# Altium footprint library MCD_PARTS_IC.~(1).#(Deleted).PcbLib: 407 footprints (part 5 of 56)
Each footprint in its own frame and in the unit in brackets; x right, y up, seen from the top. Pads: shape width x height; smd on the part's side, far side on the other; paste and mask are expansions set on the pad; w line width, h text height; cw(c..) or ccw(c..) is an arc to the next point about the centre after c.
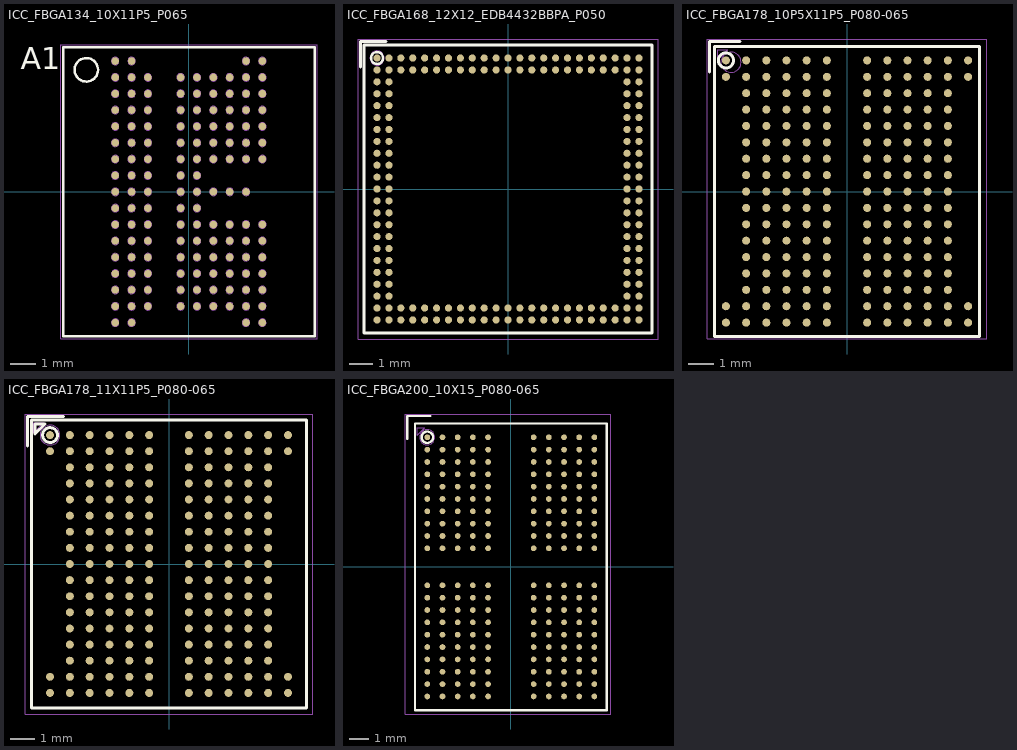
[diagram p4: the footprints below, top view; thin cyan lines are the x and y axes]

## ICC_FBGA134_10X11P5_P065 [mm] "MCD-02167"
height 0.8
pads (134):
  round 0.3 smd mask+0.05: A1(-2.925,5.2) A2(-2.275,5.2) A9(2.275,5.2) A10(2.925,5.2) B1(-2.925,4.55) B2(-2.275,4.55) B3(-1.625,4.55) B5(-0.325,4.55) B6(0.325,4.55) B7(0.975,4.55) B8(1.625,4.55) B9(2.275,4.55) B10(2.925,4.55) C1(-2.925,3.9) C2(-2.275,3.9) C3(-1.625,3.9) C5(-0.325,3.9) C6(0.325,3.9) C7(0.975,3.9) C8(1.625,3.9) C9(2.275,3.9) C10(2.925,3.9) D1(-2.925,3.25) D2(-2.275,3.25) D3(-1.625,3.25) D5(-0.325,3.25) D6(0.325,3.25) D7(0.975,3.25) D8(1.625,3.25) D9(2.275,3.25) D10(2.925,3.25) E1(-2.925,2.6) E2(-2.275,2.6) E3(-1.625,2.6) E5(-0.325,2.6) E6(0.325,2.6) E7(0.975,2.6) E8(1.625,2.6) E9(2.275,2.6) E10(2.925,2.6) F1(-2.925,1.95) F2(-2.275,1.95) F3(-1.625,1.95) F5(-0.325,1.95) F6(0.325,1.95) F7(0.975,1.95) F8(1.625,1.95) F9(2.275,1.95) F10(2.925,1.95) G1(-2.925,1.3) G2(-2.275,1.3) G3(-1.625,1.3) G5(-0.325,1.3) G6(0.325,1.3) G7(0.975,1.3) G8(1.625,1.3) G9(2.275,1.3) G10(2.925,1.3) H1(-2.925,0.65) H2(-2.275,0.65) H3(-1.625,0.65) H5(-0.325,0.65) H6(0.325,0.65) J1(-2.925,0) J2(-2.275,0) J3(-1.625,0) J5(-0.325,0) J6(0.325,0) J7(0.975,0) J8(1.625,0) J9(2.275,0) K1(-2.925,-0.65) K2(-2.275,-0.65) K3(-1.625,-0.65) K5(-0.325,-0.65) K6(0.325,-0.65) L1(-2.925,-1.3) L2(-2.275,-1.3) L3(-1.625,-1.3) L5(-0.325,-1.3) L6(0.325,-1.3) L7(0.975,-1.3) L8(1.625,-1.3) L9(2.275,-1.3) L10(2.925,-1.3) M1(-2.925,-1.95) M2(-2.275,-1.95) M3(-1.625,-1.95) M5(-0.325,-1.95) M6(0.325,-1.95) M7(0.975,-1.95) M8(1.625,-1.95) M9(2.275,-1.95) M10(2.925,-1.95) N1(-2.925,-2.6) N2(-2.275,-2.6) N3(-1.625,-2.6) N5(-0.325,-2.6) N6(0.325,-2.6) N7(0.975,-2.6) N8(1.625,-2.6) N9(2.275,-2.6) N10(2.925,-2.6) P1(-2.925,-3.25) P2(-2.275,-3.25) P3(-1.625,-3.25) P5(-0.325,-3.25) P6(0.325,-3.25) P7(0.975,-3.25) P8(1.625,-3.25) P9(2.275,-3.25) P10(2.925,-3.25) R1(-2.925,-3.9) R2(-2.275,-3.9) R3(-1.625,-3.9) R5(-0.325,-3.9) R6(0.325,-3.9) R7(0.975,-3.9) R8(1.625,-3.9) R9(2.275,-3.9) R10(2.925,-3.9) T1(-2.925,-4.55) T2(-2.275,-4.55) T3(-1.625,-4.55) T5(-0.325,-4.55) T6(0.325,-4.55) T7(0.975,-4.55) T8(1.625,-4.55) T9(2.275,-4.55) T10(2.925,-4.55) U1(-2.925,-5.2) U2(-2.275,-5.2) U9(2.275,-5.2) U10(2.925,-5.2)
Top Overlay:
  circle w0.1: c-4.075,4.85 r0.467
  lines w0.1: -5,-5.75 5,-5.75 5,5.75 -5,5.75 -5,-5.75
  text "A1" at -6.675,4.575 h1.5
M14-Top Assembly:
  circle w0.01: c-2.925,-5.2 r0.15
  circle w0.01: c-2.275,-5.2 r0.15
  circle w0.01: c2.275,-5.2 r0.15
  circle w0.01: c2.925,-5.2 r0.15
  circle w0.01: c-2.925,-4.55 r0.15
  circle w0.01: c-2.275,-4.55 r0.15
  circle w0.01: c-1.625,-4.55 r0.15
  circle w0.01: c-0.325,-4.55 r0.15
  circle w0.01: c0.325,-4.55 r0.15
  circle w0.01: c0.975,-4.55 r0.15
  circle w0.01: c1.625,-4.55 r0.15
  circle w0.01: c2.275,-4.55 r0.15
  circle w0.01: c2.925,-4.55 r0.15
  circle w0.01: c-2.925,-3.9 r0.15
  circle w0.01: c-2.275,-3.9 r0.15
  circle w0.01: c-1.625,-3.9 r0.15
  circle w0.01: c-0.325,-3.9 r0.15
  circle w0.01: c0.325,-3.9 r0.15
  circle w0.01: c0.975,-3.9 r0.15
  circle w0.01: c1.625,-3.9 r0.15
  circle w0.01: c2.275,-3.9 r0.15
  circle w0.01: c2.925,-3.9 r0.15
  circle w0.01: c-2.925,-3.25 r0.15
  circle w0.01: c-2.275,-3.25 r0.15
  circle w0.01: c-1.625,-3.25 r0.15
  circle w0.01: c-0.325,-3.25 r0.15
  circle w0.01: c0.325,-3.25 r0.15
  circle w0.01: c0.975,-3.25 r0.15
  circle w0.01: c1.625,-3.25 r0.15
  circle w0.01: c2.275,-3.25 r0.15
  circle w0.01: c2.925,-3.25 r0.15
  circle w0.01: c-2.925,-2.6 r0.15
  circle w0.01: c-2.275,-2.6 r0.15
  circle w0.01: c-1.625,-2.6 r0.15
  circle w0.01: c-0.325,-2.6 r0.15
  circle w0.01: c0.325,-2.6 r0.15
  circle w0.01: c0.975,-2.6 r0.15
  circle w0.01: c1.625,-2.6 r0.15
  circle w0.01: c2.275,-2.6 r0.15
  circle w0.01: c2.925,-2.6 r0.15
  circle w0.01: c-2.925,-1.95 r0.15
  circle w0.01: c-2.275,-1.95 r0.15
  circle w0.01: c-1.625,-1.95 r0.15
  circle w0.01: c-0.325,-1.95 r0.15
  circle w0.01: c0.325,-1.95 r0.15
  circle w0.01: c0.975,-1.95 r0.15
  circle w0.01: c1.625,-1.95 r0.15
  circle w0.01: c2.275,-1.95 r0.15
  circle w0.01: c2.925,-1.95 r0.15
  circle w0.01: c-2.925,-1.3 r0.15
  circle w0.01: c-2.275,-1.3 r0.15
  circle w0.01: c-1.625,-1.3 r0.15
  circle w0.01: c-0.325,-1.3 r0.15
  circle w0.01: c0.325,-1.3 r0.15
  circle w0.01: c0.975,-1.3 r0.15
  circle w0.01: c1.625,-1.3 r0.15
  circle w0.01: c2.275,-1.3 r0.15
  circle w0.01: c2.925,-1.3 r0.15
  circle w0.01: c-2.925,-0.65 r0.15
  circle w0.01: c-2.275,-0.65 r0.15
  circle w0.01: c-1.625,-0.65 r0.15
  circle w0.01: c-0.325,-0.65 r0.15
  circle w0.01: c0.325,-0.65 r0.15
  circle w0.01: c-2.925,0 r0.15
  circle w0.01: c-2.275,0 r0.15
  circle w0.01: c-1.625,0 r0.15
  circle w0.01: c-0.325,0 r0.15
  circle w0.01: c0.325,0 r0.15
  circle w0.01: c0.975,0 r0.15
  circle w0.01: c1.625,0 r0.15
  circle w0.01: c2.275,0 r0.15
  circle w0.01: c-2.925,0.65 r0.15
  circle w0.01: c-2.275,0.65 r0.15
  circle w0.01: c-1.625,0.65 r0.15
  circle w0.01: c-0.325,0.65 r0.15
  circle w0.01: c0.325,0.65 r0.15
  circle w0.01: c-2.925,1.3 r0.15
  circle w0.01: c-2.275,1.3 r0.15
  circle w0.01: c-1.625,1.3 r0.15
  circle w0.01: c-0.325,1.3 r0.15
  circle w0.01: c0.325,1.3 r0.15
  circle w0.01: c0.975,1.3 r0.15
  circle w0.01: c1.625,1.3 r0.15
  circle w0.01: c2.275,1.3 r0.15
  circle w0.01: c2.925,1.3 r0.15
  circle w0.01: c-2.925,1.95 r0.15
  circle w0.01: c-2.275,1.95 r0.15
  circle w0.01: c-1.625,1.95 r0.15
  circle w0.01: c-0.325,1.95 r0.15
  circle w0.01: c0.325,1.95 r0.15
  circle w0.01: c0.975,1.95 r0.15
  circle w0.01: c1.625,1.95 r0.15
  circle w0.01: c2.275,1.95 r0.15
  circle w0.01: c2.925,1.95 r0.15
  circle w0.01: c-2.925,2.6 r0.15
  circle w0.01: c-2.275,2.6 r0.15
  circle w0.01: c-1.625,2.6 r0.15
  circle w0.01: c-0.325,2.6 r0.15
  circle w0.01: c0.325,2.6 r0.15
  circle w0.01: c0.975,2.6 r0.15
  circle w0.01: c1.625,2.6 r0.15
  circle w0.01: c2.275,2.6 r0.15
  circle w0.01: c2.925,2.6 r0.15
  circle w0.01: c-2.925,3.25 r0.15
  circle w0.01: c-2.275,3.25 r0.15
  circle w0.01: c-1.625,3.25 r0.15
  circle w0.01: c-0.325,3.25 r0.15
  circle w0.01: c0.325,3.25 r0.15
  circle w0.01: c0.975,3.25 r0.15
  circle w0.01: c1.625,3.25 r0.15
  circle w0.01: c2.275,3.25 r0.15
  circle w0.01: c2.925,3.25 r0.15
  circle w0.01: c-2.925,3.9 r0.15
  circle w0.01: c-2.275,3.9 r0.15
  circle w0.01: c-1.625,3.9 r0.15
  circle w0.01: c-0.325,3.9 r0.15
  circle w0.01: c0.325,3.9 r0.15
  circle w0.01: c0.975,3.9 r0.15
  circle w0.01: c1.625,3.9 r0.15
  circle w0.01: c2.275,3.9 r0.15
  circle w0.01: c2.925,3.9 r0.15
  circle w0.01: c2.925,4.55 r0.15
  circle w0.01: c2.275,4.55 r0.15
  circle w0.01: c1.625,4.55 r0.15
  circle w0.01: c0.975,4.55 r0.15
  circle w0.01: c0.325,4.55 r0.15
  circle w0.01: c-0.325,4.55 r0.15
  circle w0.01: c-1.625,4.55 r0.15
  circle w0.01: c-2.275,4.55 r0.15
  circle w0.01: c-2.925,4.55 r0.15
  circle w0.01: c2.925,5.2 r0.15
  circle w0.01: c2.275,5.2 r0.15
  circle w0.01: c-2.275,5.2 r0.15
  circle w0.01: c-2.925,5.2 r0.15
  circle w0.01: c-4.075,4.85 r0.467
  lines w0.01: -5,-5.75 5,-5.75 5,5.75 -5,5.75 -5,-5.75
  text "A1" at -3.325,4.975 h0.7
  text "'.Designator'" at -2,-0.5 h0.75
M16-Top Courtyard:
  lines w0.01: -5.1,-5.85 5.1,-5.85 5.1,5.85 -5.1,5.85 -5.1,-5.85
3D body "User Library-FBGA 134 pin.STEP": height 0.88, standoff -0.02, extent -5,-5.75 5,5.75
3D body: height 0.81, standoff 0.8, extent -4.538,4.384 -3.608,5.316
3D body: height 0.8, standoff 0, extent -5,-5.75 5,5.75

## ICC_FBGA168_12X12_EDB4432BBPA_P050 [mm]
height 0.8
pads (168):
  round 0.3 smd mask+0.05: A1(-5.5,5.5) A2(-5,5.5) A3(-4.5,5.5) A4(-4,5.5) A5(-3.5,5.5) A6(-3,5.5) A7(-2.5,5.5) A8(-2,5.5) A9(-1.5,5.5) A10(-1,5.5) A11(-0.5,5.5) A12(0,5.5) A13(0.5,5.5) A14(1,5.5) A15(1.5,5.5) A16(2,5.5) A17(2.5,5.5) A18(3,5.5) A19(3.5,5.5) A20(4,5.5) A21(4.5,5.5) A22(5,5.5) A23(5.5,5.5) AA1(-5.5,-4.5) AA2(-5,-4.5) AA22(5,-4.5) AA23(5.5,-4.5) AB1(-5.5,-5) AB2(-5,-5) AB3(-4.5,-5) AB4(-4,-5) AB5(-3.5,-5) AB6(-3,-5) AB7(-2.5,-5) AB8(-2,-5) AB9(-1.5,-5) AB10(-1,-5) AB11(-0.5,-5) AB12(0,-5) AB13(0.5,-5) AB14(1,-5) AB15(1.5,-5) AB16(2,-5) AB17(2.5,-5) AB18(3,-5) AB19(3.5,-5) AB20(4,-5) AB21(4.5,-5) AB22(5,-5) AB23(5.5,-5) AC1(-5.5,-5.5) AC2(-5,-5.5) AC3(-4.5,-5.5) AC4(-4,-5.5) AC5(-3.5,-5.5) AC6(-3,-5.5) AC7(-2.5,-5.5) AC8(-2,-5.5) AC9(-1.5,-5.5) AC10(-1,-5.5) AC11(-0.5,-5.5) AC12(0,-5.5) AC13(0.5,-5.5) AC14(1,-5.5) AC15(1.5,-5.5) AC16(2,-5.5) AC17(2.5,-5.5) AC18(3,-5.5) AC19(3.5,-5.5) AC20(4,-5.5) AC21(4.5,-5.5) AC22(5,-5.5) AC23(5.5,-5.5) B1(-5.5,5) B2(-5,5) B3(-4.5,5) B4(-4,5) B5(-3.5,5) B6(-3,5) B7(-2.5,5) B8(-2,5) B9(-1.5,5) B10(-1,5) B11(-0.5,5) B12(0,5) B13(0.5,5) B14(1,5) B15(1.5,5) B16(2,5) B17(2.5,5) B18(3,5) B19(3.5,5) B20(4,5) B21(4.5,5) B22(5,5) B23(5.5,5) C1(-5.5,4.5) C2(-5,4.5) C22(5,4.5) C23(5.5,4.5) D1(-5.5,4) D2(-5,4) D22(5,4) D23(5.5,4) E1(-5.5,3.5) E2(-5,3.5) E22(5,3.5) E23(5.5,3.5) F1(-5.5,3) F2(-5,3) F22(5,3) F23(5.5,3) G1(-5.5,2.5) G2(-5,2.5) G22(5,2.5) G23(5.5,2.5) H1(-5.5,2) H2(-5,2) H22(5,2) H23(5.5,2) J1(-5.5,1.5) J2(-5,1.5) J22(5,1.5) J23(5.5,1.5) K1(-5.5,1) K2(-5,1) K22(5,1) K23(5.5,1) L1(-5.5,0.5) L2(-5,0.5) L22(5,0.5) L23(5.5,0.5) M1(-5.5,0) M2(-5,0) M22(5,0) M23(5.5,0) N1(-5.5,-0.5) N2(-5,-0.5) N22(5,-0.5) N23(5.5,-0.5) P1(-5.5,-1) P2(-5,-1) P22(5,-1) P23(5.5,-1) R1(-5.5,-1.5) R2(-5,-1.5) R22(5,-1.5) R23(5.5,-1.5) T1(-5.5,-2) T2(-5,-2) T22(5,-2) T23(5.5,-2) U1(-5.5,-2.5) U2(-5,-2.5) U22(5,-2.5) U23(5.5,-2.5) V1(-5.5,-3) V2(-5,-3) V22(5,-3) V23(5.5,-3) W1(-5.5,-3.5) W2(-5,-3.5) W22(5,-3.5) W23(5.5,-3.5) Y1(-5.5,-4) Y2(-5,-4) Y22(5,-4) Y23(5.5,-4)
Top Overlay:
  lines w0.1: -5.25,5.5 cw(c-5.5,5.5) -5.251,5.517
  lines w0.12: -6.2,5.125 -6.2,6.2 -5.125,6.2 ; -6.05,-6.05 -6.05,6.05 6.05,6.05 6.05,-6.05 -6.05,-6.05
M14-Top Assembly:
  circle w0.01: c-5.5,5.5 r0.3
  lines w0.01: -6.05,-6.05 -6.05,6.05 6.05,6.05 6.05,-6.05 -6.05,-6.05
  text "A1" at -5.85,5.275 h0.75
  text "'.Designator'" at -2,-0.5 h0.75
M16-Top Courtyard:
  lines w0.01: -6.3,-6.3 -6.3,6.3 6.3,6.3 6.3,-6.3 -6.3,-6.3
3D body: height 1.2, standoff 0, extent -6.355,-7.555 1.755,6.555
3D body: height 0.8, standoff 0, extent -6.05,-6.05 6.05,6.05
3D body: height 0.9, standoff 0.8, extent -5.548,4.951 -4.95,5.549

## ICC_FBGA178_10P5X11P5_P080-065 [mm] "MCD-02180"
height 0.83
pads (178):
  round 0.32 smd mask+0.05: A1(-4.8,5.2) A2(-4,5.2) A3(-3.2,5.2) A4(-2.4,5.2) A5(-1.6,5.2) A6(-0.8,5.2) A8(0.8,5.2) A9(1.6,5.2) A10(2.4,5.2) A11(3.2,5.2) A12(4,5.2) A13(4.8,5.2) B1(-4.8,4.55) B2(-4,4.55) B3(-3.2,4.55) B4(-2.4,4.55) B5(-1.6,4.55) B6(-0.8,4.55) B8(0.8,4.55) B9(1.6,4.55) B10(2.4,4.55) B11(3.2,4.55) B12(4,4.55) B13(4.8,4.55) C2(-4,3.9) C3(-3.2,3.9) C4(-2.4,3.9) C5(-1.6,3.9) C6(-0.8,3.9) C8(0.8,3.9) C9(1.6,3.9) C10(2.4,3.9) C11(3.2,3.9) C12(4,3.9) D2(-4,3.25) D3(-3.2,3.25) D4(-2.4,3.25) D5(-1.6,3.25) D6(-0.8,3.25) D8(0.8,3.25) D9(1.6,3.25) D10(2.4,3.25) D11(3.2,3.25) D12(4,3.25) E2(-4,2.6) E3(-3.2,2.6) E4(-2.4,2.6) E5(-1.6,2.6) E6(-0.8,2.6) E8(0.8,2.6) E9(1.6,2.6) E10(2.4,2.6) E11(3.2,2.6) E12(4,2.6) F2(-4,1.95) F3(-3.2,1.95) F4(-2.4,1.95) F5(-1.6,1.95) F6(-0.8,1.95) F8(0.8,1.95) F9(1.6,1.95) F10(2.4,1.95) F11(3.2,1.95) F12(4,1.95) G2(-4,1.3) G3(-3.2,1.3) G4(-2.4,1.3) G5(-1.6,1.3) G6(-0.8,1.3) G8(0.8,1.3) G9(1.6,1.3) G10(2.4,1.3) G11(3.2,1.3) G12(4,1.3) H2(-4,0.65) H3(-3.2,0.65) H4(-2.4,0.65) H5(-1.6,0.65) H6(-0.8,0.65) H8(0.8,0.65) H9(1.6,0.65) H10(2.4,0.65) H11(3.2,0.65) H12(4,0.65) J2(-4,0) J3(-3.2,0) J4(-2.4,0) J5(-1.6,0) J6(-0.8,0) J8(0.8,0) J9(1.6,0) J10(2.4,0) J11(3.2,0) J12(4,0) K2(-4,-0.65) K3(-3.2,-0.65) K4(-2.4,-0.65) K5(-1.6,-0.65) K6(-0.8,-0.65) K8(0.8,-0.65) K9(1.6,-0.65) K10(2.4,-0.65) K11(3.2,-0.65) K12(4,-0.65) L2(-4,-1.3) L3(-3.2,-1.3) L4(-2.4,-1.3) L5(-1.6,-1.3) L6(-0.8,-1.3) L8(0.8,-1.3) L9(1.6,-1.3) L10(2.4,-1.3) L11(3.2,-1.3) L12(4,-1.3) M2(-4,-1.95) M3(-3.2,-1.95) M4(-2.4,-1.95) M5(-1.6,-1.95) M6(-0.8,-1.95) M8(0.8,-1.95) M9(1.6,-1.95) M10(2.4,-1.95) M11(3.2,-1.95) M12(4,-1.95) N2(-4,-2.6) N3(-3.2,-2.6) N4(-2.4,-2.6) N5(-1.6,-2.6) N6(-0.8,-2.6) N8(0.8,-2.6) N9(1.6,-2.6) N10(2.4,-2.6) N11(3.2,-2.6) N12(4,-2.6) P2(-4,-3.25) P3(-3.2,-3.25) P4(-2.4,-3.25) P5(-1.6,-3.25) P6(-0.8,-3.25) P8(0.8,-3.25) P9(1.6,-3.25) P10(2.4,-3.25) P11(3.2,-3.25) P12(4,-3.25) R2(-4,-3.9) R3(-3.2,-3.9) R4(-2.4,-3.9) R5(-1.6,-3.9) R6(-0.8,-3.9) R8(0.8,-3.9) R9(1.6,-3.9) R10(2.4,-3.9) R11(3.2,-3.9) R12(4,-3.9) T1(-4.8,-4.55) T2(-4,-4.55) T3(-3.2,-4.55) T4(-2.4,-4.55) T5(-1.6,-4.55) T6(-0.8,-4.55) T8(0.8,-4.55) T9(1.6,-4.55) T10(2.4,-4.55) T11(3.2,-4.55) T12(4,-4.55) T13(4.8,-4.55) U1(-4.8,-5.2) U2(-4,-5.2) U3(-3.2,-5.2) U4(-2.4,-5.2) U5(-1.6,-5.2) U6(-0.8,-5.2) U8(0.8,-5.2) U9(1.6,-5.2) U10(2.4,-5.2) U11(3.2,-5.2) U12(4,-5.2) U13(4.8,-5.2)
Top Overlay:
  circle w0.12: c-4.8,5.2 r0.3
  lines w0.12: -5.45,4.75 -5.45,5.95 -4.25,5.95 ; -5.25,-5.75 5.25,-5.75 5.25,5.75 -5.25,5.75 -5.25,-5.75
M14-Top Assembly:
  circle w0.01: c-4.6,5.125 r0.4
  lines w0.01: -5.25,-5.75 -5.25,5.75 5.25,5.75 5.25,-5.75 -5.25,-5.75 ; -5.125,5.225 -5.125,5.625 -4.725,5.625 -5.125,5.225
  text "'.Designator'" at -2,-0.5 h0.75
  text "A1" at -4.95,4.9 h0.75
M16-Top Courtyard:
  lines w0.01: -5.55,-5.85 5.55,-5.85 5.55,6.05 -5.55,6.05 -5.55,-5.85
3D body: height 1, standoff 0, extent -5.25,-5.75 5.25,5.75
3D body: height 1.05, standoff 1, extent -5.098,4.901 -4.5,5.499

## ICC_FBGA178_11X11P5_P080-065 [mm]
height 1
pads (178):
  round 0.32 smd mask+0.05: A1(-4.8,5.2) A2(-4,5.2) A3(-3.2,5.2) A4(-2.4,5.2) A5(-1.6,5.2) A6(-0.8,5.2) A8(0.8,5.2) A9(1.6,5.2) A10(2.4,5.2) A11(3.2,5.2) A12(4,5.2) A13(4.8,5.2) B1(-4.8,4.55) B2(-4,4.55) B3(-3.2,4.55) B4(-2.4,4.55) B5(-1.6,4.55) B6(-0.8,4.55) B8(0.8,4.55) B9(1.6,4.55) B10(2.4,4.55) B11(3.2,4.55) B12(4,4.55) B13(4.8,4.55) C2(-4,3.9) C3(-3.2,3.9) C4(-2.4,3.9) C5(-1.6,3.9) C6(-0.8,3.9) C8(0.8,3.9) C9(1.6,3.9) C10(2.4,3.9) C11(3.2,3.9) C12(4,3.9) D2(-4,3.25) D3(-3.2,3.25) D4(-2.4,3.25) D5(-1.6,3.25) D6(-0.8,3.25) D8(0.8,3.25) D9(1.6,3.25) D10(2.4,3.25) D11(3.2,3.25) D12(4,3.25) E2(-4,2.6) E3(-3.2,2.6) E4(-2.4,2.6) E5(-1.6,2.6) E6(-0.8,2.6) E8(0.8,2.6) E9(1.6,2.6) E10(2.4,2.6) E11(3.2,2.6) E12(4,2.6) F2(-4,1.95) F3(-3.2,1.95) F4(-2.4,1.95) F5(-1.6,1.95) F6(-0.8,1.95) F8(0.8,1.95) F9(1.6,1.95) F10(2.4,1.95) F11(3.2,1.95) F12(4,1.95) G2(-4,1.3) G3(-3.2,1.3) G4(-2.4,1.3) G5(-1.6,1.3) G6(-0.8,1.3) G8(0.8,1.3) G9(1.6,1.3) G10(2.4,1.3) G11(3.2,1.3) G12(4,1.3) H2(-4,0.65) H3(-3.2,0.65) H4(-2.4,0.65) H5(-1.6,0.65) H6(-0.8,0.65) H8(0.8,0.65) H9(1.6,0.65) H10(2.4,0.65) H11(3.2,0.65) H12(4,0.65) J2(-4,0) J3(-3.2,0) J4(-2.4,0) J5(-1.6,0) J6(-0.8,0) J8(0.8,0) J9(1.6,0) J10(2.4,0) J11(3.2,0) J12(4,0) K2(-4,-0.65) K3(-3.2,-0.65) K4(-2.4,-0.65) K5(-1.6,-0.65) K6(-0.8,-0.65) K8(0.8,-0.65) K9(1.6,-0.65) K10(2.4,-0.65) K11(3.2,-0.65) K12(4,-0.65) L2(-4,-1.3) L3(-3.2,-1.3) L4(-2.4,-1.3) L5(-1.6,-1.3) L6(-0.8,-1.3) L8(0.8,-1.3) L9(1.6,-1.3) L10(2.4,-1.3) L11(3.2,-1.3) L12(4,-1.3) M2(-4,-1.95) M3(-3.2,-1.95) M4(-2.4,-1.95) M5(-1.6,-1.95) M6(-0.8,-1.95) M8(0.8,-1.95) M9(1.6,-1.95) M10(2.4,-1.95) M11(3.2,-1.95) M12(4,-1.95) N2(-4,-2.6) N3(-3.2,-2.6) N4(-2.4,-2.6) N5(-1.6,-2.6) N6(-0.8,-2.6) N8(0.8,-2.6) N9(1.6,-2.6) N10(2.4,-2.6) N11(3.2,-2.6) N12(4,-2.6) P2(-4,-3.25) P3(-3.2,-3.25) P4(-2.4,-3.25) P5(-1.6,-3.25) P6(-0.8,-3.25) P8(0.8,-3.25) P9(1.6,-3.25) P10(2.4,-3.25) P11(3.2,-3.25) P12(4,-3.25) R2(-4,-3.9) R3(-3.2,-3.9) R4(-2.4,-3.9) R5(-1.6,-3.9) R6(-0.8,-3.9) R8(0.8,-3.9) R9(1.6,-3.9) R10(2.4,-3.9) R11(3.2,-3.9) R12(4,-3.9) T1(-4.8,-4.55) T2(-4,-4.55) T3(-3.2,-4.55) T4(-2.4,-4.55) T5(-1.6,-4.55) T6(-0.8,-4.55) T8(0.8,-4.55) T9(1.6,-4.55) T10(2.4,-4.55) T11(3.2,-4.55) T12(4,-4.55) T13(4.8,-4.55) U1(-4.8,-5.2) U2(-4,-5.2) U3(-3.2,-5.2) U4(-2.4,-5.2) U5(-1.6,-5.2) U6(-0.8,-5.2) U8(0.8,-5.2) U9(1.6,-5.2) U10(2.4,-5.2) U11(3.2,-5.2) U12(4,-5.2) U13(4.8,-5.2)
Top Overlay:
  circle w0.12: c-4.8,5.2 r0.3
  lines w0.12: -5.7,4.75 -5.7,5.95 -4.25,5.95 ; -5.55,-5.8 -5.55,5.8 5.55,5.8 5.55,-5.8 -5.55,-5.8 ; -5.4,5.25 -5,5.65 -5.4,5.65 -5.4,5.25
M14-Top Assembly:
  circle w0.01: c-4.8,5.2 r0.4
  lines w0.01: -5.55,-5.8 5.55,-5.8 5.55,5.8 -5.55,5.8 -5.55,-5.8 ; -5.45,5.3 -5.05,5.7 -5.45,5.7 -5.45,5.3
  text "A1" at -5.15,4.975 h0.75
  text "'.Designator'" at -2,-0.5 h0.75
M16-Top Courtyard:
  lines w0.01: -5.8,-6.05 -5.8,6.05 5.8,6.05 5.8,-6.05 -5.8,-6.05
3D body: height 1.05, standoff 1, extent -5.098,4.901 -4.5,5.499
3D body: height 1, standoff 0, extent -5.55,-5.8 5.55,5.8

## ICC_FBGA200_10X15_P080-065 [mm] "MCD-02576"
height 1
pads (200):
  round 0.3 smd mask+0.05: A1(-4.4,6.825) A2(-3.6,6.825) A3(-2.8,6.825) A4(-2,6.825) A5(-1.2,6.825) A8(1.2,6.825) A9(2,6.825) A10(2.8,6.825) A11(3.6,6.825) A12(4.4,6.825) AA1(-4.4,-6.175) AA2(-3.6,-6.175) AA3(-2.8,-6.175) AA4(-2,-6.175) AA5(-1.2,-6.175) AA8(1.2,-6.175) AA9(2,-6.175) AA10(2.8,-6.175) AA11(3.6,-6.175) AA12(4.4,-6.175) AB1(-4.4,-6.825) AB2(-3.6,-6.825) AB3(-2.8,-6.825) AB4(-2,-6.825) AB5(-1.2,-6.825) AB8(1.2,-6.825) AB9(2,-6.825) AB10(2.8,-6.825) AB11(3.6,-6.825) AB12(4.4,-6.825) B1(-4.4,6.175) B2(-3.6,6.175) B3(-2.8,6.175) B4(-2,6.175) B5(-1.2,6.175) B8(1.2,6.175) B9(2,6.175) B10(2.8,6.175) B11(3.6,6.175) B12(4.4,6.175) C1(-4.4,5.525) C2(-3.6,5.525) C3(-2.8,5.525) C4(-2,5.525) C5(-1.2,5.525) C8(1.2,5.525) C9(2,5.525) C10(2.8,5.525) C11(3.6,5.525) C12(4.4,5.525) D1(-4.4,4.875) D2(-3.6,4.875) D3(-2.8,4.875) D4(-2,4.875) D5(-1.2,4.875) D8(1.2,4.875) D9(2,4.875) D10(2.8,4.875) D11(3.6,4.875) D12(4.4,4.875) E1(-4.4,4.225) E2(-3.6,4.225) E3(-2.8,4.225) E4(-2,4.225) E5(-1.2,4.225) E8(1.2,4.225) E9(2,4.225) E10(2.8,4.225) E11(3.6,4.225) E12(4.4,4.225) F1(-4.4,3.575) F2(-3.6,3.575) F3(-2.8,3.575) F4(-2,3.575) F5(-1.2,3.575) F8(1.2,3.575) F9(2,3.575) F10(2.8,3.575) F11(3.6,3.575) F12(4.4,3.575) G1(-4.4,2.925) G2(-3.6,2.925) G3(-2.8,2.925) G4(-2,2.925) G5(-1.2,2.925) G8(1.2,2.925) G9(2,2.925) G10(2.8,2.925) G11(3.6,2.925) G12(4.4,2.925) H1(-4.4,2.275) H2(-3.6,2.275) H3(-2.8,2.275) H4(-2,2.275) H5(-1.2,2.275) H8(1.2,2.275) H9(2,2.275) H10(2.8,2.275) H11(3.6,2.275) H12(4.4,2.275) J1(-4.4,1.625) J2(-3.6,1.625) J3(-2.8,1.625) J4(-2,1.625) J5(-1.2,1.625) J8(1.2,1.625) J9(2,1.625) J10(2.8,1.625) J11(3.6,1.625) J12(4.4,1.625) K1(-4.4,0.975) K2(-3.6,0.975) K3(-2.8,0.975) K4(-2,0.975) K5(-1.2,0.975) K8(1.2,0.975) K9(2,0.975) K10(2.8,0.975) K11(3.6,0.975) K12(4.4,0.975) N1(-4.4,-0.975) N2(-3.6,-0.975) N3(-2.8,-0.975) N4(-2,-0.975) N5(-1.2,-0.975) N8(1.2,-0.975) N9(2,-0.975) N10(2.8,-0.975) N11(3.6,-0.975) N12(4.4,-0.975) P1(-4.4,-1.625) P2(-3.6,-1.625) P3(-2.8,-1.625) P4(-2,-1.625) P5(-1.2,-1.625) P8(1.2,-1.625) P9(2,-1.625) P10(2.8,-1.625) P11(3.6,-1.625) P12(4.4,-1.625) R1(-4.4,-2.275) R2(-3.6,-2.275) R3(-2.8,-2.275) R4(-2,-2.275) R5(-1.2,-2.275) R8(1.2,-2.275) R9(2,-2.275) R10(2.8,-2.275) R11(3.6,-2.275) R12(4.4,-2.275) T1(-4.4,-2.925) T2(-3.6,-2.925) T3(-2.8,-2.925) T4(-2,-2.925) T5(-1.2,-2.925) T8(1.2,-2.925) T9(2,-2.925) T10(2.8,-2.925) T11(3.6,-2.925) T12(4.4,-2.925) U1(-4.4,-3.575) U2(-3.6,-3.575) U3(-2.8,-3.575) U4(-2,-3.575) U5(-1.2,-3.575) U8(1.2,-3.575) U9(2,-3.575) U10(2.8,-3.575) U11(3.6,-3.575) U12(4.4,-3.575) V1(-4.4,-4.225) V2(-3.6,-4.225) V3(-2.8,-4.225) V4(-2,-4.225) V5(-1.2,-4.225) V8(1.2,-4.225) V9(2,-4.225) V10(2.8,-4.225) V11(3.6,-4.225) V12(4.4,-4.225) W1(-4.4,-4.875) W2(-3.6,-4.875) W3(-2.8,-4.875) W4(-2,-4.875) W5(-1.2,-4.875) W8(1.2,-4.875) W9(2,-4.875) W10(2.8,-4.875) W11(3.6,-4.875) W12(4.4,-4.875) Y1(-4.4,-5.525) Y2(-3.6,-5.525) Y3(-2.8,-5.525) Y4(-2,-5.525) Y5(-1.2,-5.525) Y8(1.2,-5.525) Y9(2,-5.525) Y10(2.8,-5.525) Y11(3.6,-5.525) Y12(4.4,-5.525)
Top Overlay:
  circle w0.12: c-4.4,6.825 r0.3
  lines w0.12: -5.45,6.75 -5.45,7.95 -4.25,7.95 ; -5.05,-7.55 5.05,-7.55 5.05,7.55 -5.05,7.55 -5.05,-7.55
M14-Top Assembly:
  circle w0.01: c-4.4,6.825 r0.4
  lines w0.01: -5.05,-7.55 -5.05,7.55 5.05,7.55 5.05,-7.55 -5.05,-7.55 ; -4.925,6.925 -4.925,7.325 -4.525,7.325 -4.925,6.925
  text "'.Designator'" at -2,-0.5 h0.75
  text "A1" at -4.75,6.6 h0.75
M16-Top Courtyard:
  lines w0.01: -5.55,-7.75 5.25,-7.75 5.25,8.05 -5.55,8.05 -5.55,-7.75
3D body: height 0.36, standoff -0.04, extent 4.201,-7.022 4.6,-6.628
3D body: height 0.36, standoff -0.04, extent 3.401,-7.022 3.8,-6.628
3D body: height 0.36, standoff -0.04, extent 2.601,-7.022 3,-6.628
3D body: height 0.36, standoff -0.04, extent 1.801,-7.022 2.2,-6.628
3D body: height 0.36, standoff -0.04, extent 1.001,-7.022 1.4,-6.628
3D body: height 0.36, standoff -0.04, extent -1.399,-7.022 -1,-6.628
3D body: height 0.36, standoff -0.04, extent -2.199,-7.022 -1.8,-6.628
3D body: height 0.36, standoff -0.04, extent -2.999,-7.022 -2.6,-6.628
3D body: height 0.36, standoff -0.04, extent -3.799,-7.022 -3.4,-6.628
3D body: height 0.36, standoff -0.04, extent -4.599,-7.022 -4.2,-6.628
3D body: height 0.36, standoff -0.04, extent 4.201,-6.372 4.6,-5.978
3D body: height 0.36, standoff -0.04, extent 3.401,-6.372 3.8,-5.978
3D body: height 0.36, standoff -0.04, extent 2.601,-6.372 3,-5.978
3D body: height 0.36, standoff -0.04, extent 1.801,-6.372 2.2,-5.978
3D body: height 0.36, standoff -0.04, extent 1.001,-6.372 1.4,-5.978
3D body: height 0.36, standoff -0.04, extent -1.399,-6.372 -1,-5.978
3D body: height 0.36, standoff -0.04, extent -2.199,-6.372 -1.8,-5.978
3D body: height 0.36, standoff -0.04, extent -2.999,-6.372 -2.6,-5.978
3D body: height 0.36, standoff -0.04, extent -3.799,-6.372 -3.4,-5.978
3D body: height 0.36, standoff -0.04, extent -4.599,-6.372 -4.2,-5.978
3D body: height 0.36, standoff -0.04, extent 4.201,-5.722 4.6,-5.328
3D body: height 0.36, standoff -0.04, extent 3.401,-5.722 3.8,-5.328
3D body: height 0.36, standoff -0.04, extent 2.601,-5.722 3,-5.328
3D body: height 0.36, standoff -0.04, extent 1.801,-5.722 2.2,-5.328
3D body: height 0.36, standoff -0.04, extent 1.001,-5.722 1.4,-5.328
3D body: height 0.36, standoff -0.04, extent -1.399,-5.722 -1,-5.328
3D body: height 0.36, standoff -0.04, extent -2.199,-5.722 -1.8,-5.328
3D body: height 0.36, standoff -0.04, extent -2.999,-5.722 -2.6,-5.328
3D body: height 0.36, standoff -0.04, extent -3.799,-5.722 -3.4,-5.328
3D body: height 0.36, standoff -0.04, extent -4.599,-5.722 -4.2,-5.328
3D body: height 0.36, standoff -0.04, extent 4.201,-5.072 4.6,-4.678
3D body: height 0.36, standoff -0.04, extent 3.401,-5.072 3.8,-4.678
3D body: height 0.36, standoff -0.04, extent 2.601,-5.072 3,-4.678
3D body: height 0.36, standoff -0.04, extent 1.801,-5.072 2.2,-4.678
3D body: height 0.36, standoff -0.04, extent 1.001,-5.072 1.4,-4.678
3D body: height 0.36, standoff -0.04, extent -1.399,-5.072 -1,-4.678
3D body: height 0.36, standoff -0.04, extent -2.199,-5.072 -1.8,-4.678
3D body: height 0.36, standoff -0.04, extent -2.999,-5.072 -2.6,-4.678
3D body: height 0.36, standoff -0.04, extent -3.799,-5.072 -3.4,-4.678
3D body: height 0.36, standoff -0.04, extent -4.599,-5.072 -4.2,-4.678
3D body: height 0.36, standoff -0.04, extent 4.201,-4.422 4.6,-4.028
3D body: height 0.36, standoff -0.04, extent 3.401,-4.422 3.8,-4.028
3D body: height 0.36, standoff -0.04, extent 2.601,-4.422 3,-4.028
3D body: height 0.36, standoff -0.04, extent 1.801,-4.422 2.2,-4.028
3D body: height 0.36, standoff -0.04, extent 1.001,-4.422 1.4,-4.028
3D body: height 0.36, standoff -0.04, extent -1.399,-4.422 -1,-4.028
3D body: height 0.36, standoff -0.04, extent -2.199,-4.422 -1.8,-4.028
3D body: height 0.36, standoff -0.04, extent -2.999,-4.422 -2.6,-4.028
3D body: height 0.36, standoff -0.04, extent -3.799,-4.422 -3.4,-4.028
3D body: height 0.36, standoff -0.04, extent -4.599,-4.422 -4.2,-4.028
3D body: height 0.36, standoff -0.04, extent 4.201,-3.772 4.6,-3.378
3D body: height 0.36, standoff -0.04, extent 3.401,-3.772 3.8,-3.378
3D body: height 0.36, standoff -0.04, extent 2.601,-3.772 3,-3.378
3D body: height 0.36, standoff -0.04, extent 1.801,-3.772 2.2,-3.378
3D body: height 0.36, standoff -0.04, extent 1.001,-3.772 1.4,-3.378
3D body: height 0.36, standoff -0.04, extent -1.399,-3.772 -1,-3.378
3D body: height 0.36, standoff -0.04, extent -2.199,-3.772 -1.8,-3.378
3D body: height 0.36, standoff -0.04, extent -2.999,-3.772 -2.6,-3.378
3D body: height 0.36, standoff -0.04, extent -3.799,-3.772 -3.4,-3.378
3D body: height 0.36, standoff -0.04, extent -4.599,-3.772 -4.2,-3.378
3D body: height 0.36, standoff -0.04, extent 4.201,-3.122 4.6,-2.728
3D body: height 0.36, standoff -0.04, extent 3.401,-3.122 3.8,-2.728
3D body: height 0.36, standoff -0.04, extent 2.601,-3.122 3,-2.728
3D body: height 0.36, standoff -0.04, extent 1.801,-3.122 2.2,-2.728
3D body: height 0.36, standoff -0.04, extent 1.001,-3.122 1.4,-2.728
3D body: height 0.36, standoff -0.04, extent -1.399,-3.122 -1,-2.728
3D body: height 0.36, standoff -0.04, extent -2.199,-3.122 -1.8,-2.728
3D body: height 0.36, standoff -0.04, extent -2.999,-3.122 -2.6,-2.728
3D body: height 0.36, standoff -0.04, extent -3.799,-3.122 -3.4,-2.728
3D body: height 0.36, standoff -0.04, extent -4.599,-3.122 -4.2,-2.728
3D body: height 0.36, standoff -0.04, extent 4.201,-2.472 4.6,-2.078
3D body: height 0.36, standoff -0.04, extent 3.401,-2.472 3.8,-2.078
3D body: height 0.36, standoff -0.04, extent 2.601,-2.472 3,-2.078
3D body: height 0.36, standoff -0.04, extent 1.801,-2.472 2.2,-2.078
3D body: height 0.36, standoff -0.04, extent 1.001,-2.472 1.4,-2.078
3D body: height 0.36, standoff -0.04, extent -1.399,-2.472 -1,-2.078
3D body: height 0.36, standoff -0.04, extent -2.199,-2.472 -1.8,-2.078
3D body: height 0.36, standoff -0.04, extent -2.999,-2.472 -2.6,-2.078
3D body: height 0.36, standoff -0.04, extent -3.799,-2.472 -3.4,-2.078
3D body: height 0.36, standoff -0.04, extent -4.599,-2.472 -4.2,-2.078
3D body: height 0.36, standoff -0.04, extent 4.201,-1.822 4.6,-1.428
3D body: height 0.36, standoff -0.04, extent 3.401,-1.822 3.8,-1.428
3D body: height 0.36, standoff -0.04, extent 2.601,-1.822 3,-1.428
3D body: height 0.36, standoff -0.04, extent 1.801,-1.822 2.2,-1.428
3D body: height 0.36, standoff -0.04, extent 1.001,-1.822 1.4,-1.428
3D body: height 0.36, standoff -0.04, extent -1.399,-1.822 -1,-1.428
3D body: height 0.36, standoff -0.04, extent -2.199,-1.822 -1.8,-1.428
3D body: height 0.36, standoff -0.04, extent -2.999,-1.822 -2.6,-1.428
3D body: height 0.36, standoff -0.04, extent -3.799,-1.822 -3.4,-1.428
3D body: height 0.36, standoff -0.04, extent -4.599,-1.822 -4.2,-1.428
3D body: height 0.36, standoff -0.04, extent 4.201,-1.172 4.6,-0.778
3D body: height 0.36, standoff -0.04, extent 3.401,-1.172 3.8,-0.778
3D body: height 0.36, standoff -0.04, extent 2.601,-1.172 3,-0.778
3D body: height 0.36, standoff -0.04, extent 1.801,-1.172 2.2,-0.778
3D body: height 0.36, standoff -0.04, extent 1.001,-1.172 1.4,-0.778
3D body: height 0.36, standoff -0.04, extent -1.399,-1.172 -1,-0.778
3D body: height 0.36, standoff -0.04, extent -2.199,-1.172 -1.8,-0.778
3D body: height 0.36, standoff -0.04, extent -2.999,-1.172 -2.6,-0.778
3D body: height 0.36, standoff -0.04, extent -3.799,-1.172 -3.4,-0.778
3D body: height 0.36, standoff -0.04, extent -4.599,-1.172 -4.2,-0.778
3D body: height 0.36, standoff -0.04, extent 4.201,0.778 4.6,1.172
3D body: height 0.36, standoff -0.04, extent 3.401,0.778 3.8,1.172
3D body: height 0.36, standoff -0.04, extent 2.601,0.778 3,1.172
3D body: height 0.36, standoff -0.04, extent 1.801,0.778 2.2,1.172
3D body: height 0.36, standoff -0.04, extent 1.001,0.778 1.4,1.172
3D body: height 0.36, standoff -0.04, extent -1.399,0.778 -1,1.172
3D body: height 0.36, standoff -0.04, extent -2.199,0.778 -1.8,1.172
3D body: height 0.36, standoff -0.04, extent -2.999,0.778 -2.6,1.172
3D body: height 0.36, standoff -0.04, extent -3.799,0.778 -3.4,1.172
3D body: height 0.36, standoff -0.04, extent -4.599,0.778 -4.2,1.172
3D body: height 0.36, standoff -0.04, extent 4.201,1.428 4.6,1.822
3D body: height 0.36, standoff -0.04, extent 3.401,1.428 3.8,1.822
3D body: height 0.36, standoff -0.04, extent 2.601,1.428 3,1.822
3D body: height 0.36, standoff -0.04, extent 1.801,1.428 2.2,1.822
3D body: height 0.36, standoff -0.04, extent 1.001,1.428 1.4,1.822
3D body: height 0.36, standoff -0.04, extent -1.399,1.428 -1,1.822
3D body: height 0.36, standoff -0.04, extent -2.199,1.428 -1.8,1.822
3D body: height 0.36, standoff -0.04, extent -2.999,1.428 -2.6,1.822
3D body: height 0.36, standoff -0.04, extent -3.799,1.428 -3.4,1.822
3D body: height 0.36, standoff -0.04, extent -4.599,1.428 -4.2,1.822
3D body: height 0.36, standoff -0.04, extent 4.201,2.078 4.6,2.472
3D body: height 0.36, standoff -0.04, extent 3.401,2.078 3.8,2.472
3D body: height 0.36, standoff -0.04, extent 2.601,2.078 3,2.472
3D body: height 0.36, standoff -0.04, extent 1.801,2.078 2.2,2.472
3D body: height 0.36, standoff -0.04, extent 1.001,2.078 1.4,2.472
3D body: height 0.36, standoff -0.04, extent -1.399,2.078 -1,2.472
3D body: height 0.36, standoff -0.04, extent -2.199,2.078 -1.8,2.472
3D body: height 0.36, standoff -0.04, extent -2.999,2.078 -2.6,2.472
3D body: height 0.36, standoff -0.04, extent -3.799,2.078 -3.4,2.472
3D body: height 0.36, standoff -0.04, extent -4.599,2.078 -4.2,2.472
3D body: height 0.36, standoff -0.04, extent 4.201,2.728 4.6,3.122
3D body: height 0.36, standoff -0.04, extent 3.401,2.728 3.8,3.122
3D body: height 0.36, standoff -0.04, extent 2.601,2.728 3,3.122
3D body: height 0.36, standoff -0.04, extent 1.801,2.728 2.2,3.122
3D body: height 0.36, standoff -0.04, extent 1.001,2.728 1.4,3.122
3D body: height 0.36, standoff -0.04, extent -1.399,2.728 -1,3.122
3D body: height 0.36, standoff -0.04, extent -2.199,2.728 -1.8,3.122
3D body: height 0.36, standoff -0.04, extent -2.999,2.728 -2.6,3.122
3D body: height 0.36, standoff -0.04, extent -3.799,2.728 -3.4,3.122
3D body: height 0.36, standoff -0.04, extent -4.599,2.728 -4.2,3.122
3D body: height 0.36, standoff -0.04, extent 4.201,3.378 4.6,3.772
3D body: height 0.36, standoff -0.04, extent 3.401,3.378 3.8,3.772
3D body: height 0.36, standoff -0.04, extent 2.601,3.378 3,3.772
3D body: height 0.36, standoff -0.04, extent 1.801,3.378 2.2,3.772
3D body: height 0.36, standoff -0.04, extent 1.001,3.378 1.4,3.772
3D body: height 0.36, standoff -0.04, extent -1.399,3.378 -1,3.772
3D body: height 0.36, standoff -0.04, extent -2.199,3.378 -1.8,3.772
3D body: height 0.36, standoff -0.04, extent -2.999,3.378 -2.6,3.772
3D body: height 0.36, standoff -0.04, extent -3.799,3.378 -3.4,3.772
3D body: height 0.36, standoff -0.04, extent -4.599,3.378 -4.2,3.772
3D body: height 0.36, standoff -0.04, extent 4.201,4.028 4.6,4.422
3D body: height 0.36, standoff -0.04, extent 3.401,4.028 3.8,4.422
3D body: height 0.36, standoff -0.04, extent 2.601,4.028 3,4.422
3D body: height 0.36, standoff -0.04, extent 1.801,4.028 2.2,4.422
3D body: height 0.36, standoff -0.04, extent 1.001,4.028 1.4,4.422
3D body: height 0.36, standoff -0.04, extent -1.399,4.028 -1,4.422
3D body: height 0.36, standoff -0.04, extent -2.199,4.028 -1.8,4.422
3D body: height 0.36, standoff -0.04, extent -2.999,4.028 -2.6,4.422
3D body: height 0.36, standoff -0.04, extent -3.799,4.028 -3.4,4.422
3D body: height 0.36, standoff -0.04, extent -4.599,4.028 -4.2,4.422
3D body: height 0.36, standoff -0.04, extent 4.201,4.678 4.6,5.072
3D body: height 0.36, standoff -0.04, extent 3.401,4.678 3.8,5.072
3D body: height 0.36, standoff -0.04, extent 2.601,4.678 3,5.072
3D body: height 0.36, standoff -0.04, extent 1.801,4.678 2.2,5.072
3D body: height 0.36, standoff -0.04, extent 1.001,4.678 1.4,5.072
3D body: height 0.36, standoff -0.04, extent -1.399,4.678 -1,5.072
3D body: height 0.36, standoff -0.04, extent -2.199,4.678 -1.8,5.072
3D body: height 0.36, standoff -0.04, extent -2.999,4.678 -2.6,5.072
3D body: height 0.36, standoff -0.04, extent -3.799,4.678 -3.4,5.072
3D body: height 0.36, standoff -0.04, extent -4.599,4.678 -4.2,5.072
3D body: height 0.36, standoff -0.04, extent 4.201,5.328 4.6,5.722
3D body: height 0.36, standoff -0.04, extent 3.401,5.328 3.8,5.722
3D body: height 0.36, standoff -0.04, extent 2.601,5.328 3,5.722
3D body: height 0.36, standoff -0.04, extent 1.801,5.328 2.2,5.722
3D body: height 0.36, standoff -0.04, extent 1.001,5.328 1.4,5.722
3D body: height 0.36, standoff -0.04, extent -1.399,5.328 -1,5.722
3D body: height 0.36, standoff -0.04, extent -2.199,5.328 -1.8,5.722
3D body: height 0.36, standoff -0.04, extent -2.999,5.328 -2.6,5.722
3D body: height 0.36, standoff -0.04, extent -3.799,5.328 -3.4,5.722
3D body: height 0.36, standoff -0.04, extent -4.599,5.328 -4.2,5.722
3D body: height 0.36, standoff -0.04, extent 4.201,5.978 4.6,6.372
3D body: height 0.36, standoff -0.04, extent 3.401,5.978 3.8,6.372
3D body: height 0.36, standoff -0.04, extent 2.601,5.978 3,6.372
3D body: height 0.36, standoff -0.04, extent 1.801,5.978 2.2,6.372
3D body: height 0.36, standoff -0.04, extent 1.001,5.978 1.4,6.372
3D body: height 0.36, standoff -0.04, extent -1.399,5.978 -1,6.372
3D body: height 0.36, standoff -0.04, extent -2.199,5.978 -1.8,6.372
3D body: height 0.36, standoff -0.04, extent -2.999,5.978 -2.6,6.372
3D body: height 0.36, standoff -0.04, extent -3.799,5.978 -3.4,6.372
3D body: height 0.36, standoff -0.04, extent -4.599,5.978 -4.2,6.372
3D body: height 0.36, standoff -0.04, extent 4.201,6.628 4.6,7.022
3D body: height 0.36, standoff -0.04, extent 3.401,6.628 3.8,7.022
3D body: height 0.36, standoff -0.04, extent 2.601,6.628 3,7.022
3D body: height 0.36, standoff -0.04, extent 1.801,6.628 2.2,7.022
3D body: height 0.36, standoff -0.04, extent 1.001,6.628 1.4,7.022
3D body: height 0.36, standoff -0.04, extent -1.399,6.628 -1,7.022
3D body: height 0.36, standoff -0.04, extent -2.199,6.628 -1.8,7.022
3D body: height 0.36, standoff -0.04, extent -2.999,6.628 -2.6,7.022
3D body: height 0.36, standoff -0.04, extent -3.799,6.628 -3.4,7.022
3D body: height 1.05, standoff 1, extent -4.697,6.526 -4.1,7.125
3D body: height 1, standoff 0.3, extent -5.05,-7.55 5.05,7.55
3D body: height 0.36, standoff -0.04, extent -4.599,6.628 -4.2,7.022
